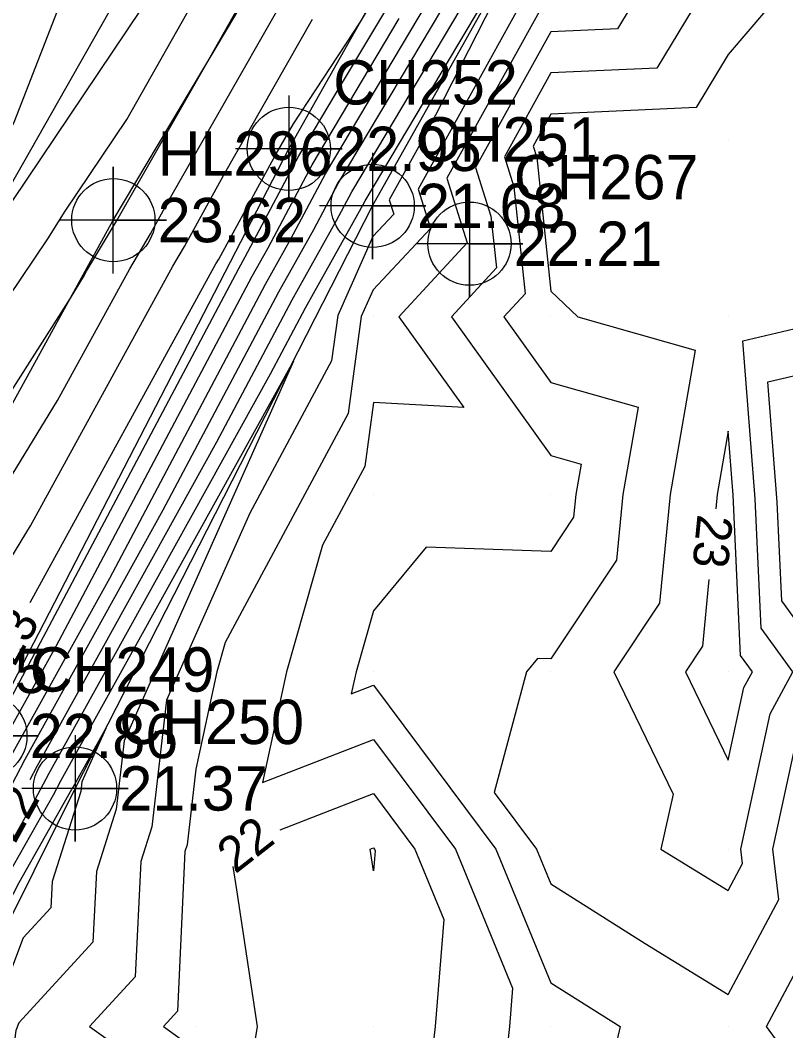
# Model space of a CAD drawing. Extents: x 2531902 to 2533249, y 715219 to 716099.
# Drawn here: x 2532990.1 to 2533033.2, y 715829.8 to 715886.7 of the extents above; entities that cross this region are included whole.
import ezdxf

# ---------------------------------------------------------------- set-up
doc = ezdxf.new("R2010")
doc.units = 0
for name, color, linetype in [('DTM Contours Major', 7, 'Continuous'), ('DTM Contours Major Text', 7, 'Continuous'), ('DTM Contours Minor', 7, 'Continuous'), ('Exist DTM Breakline', 7, 'Continuous'), ('Exist DTM Breakline Cogo Elevation', 7, 'Continuous'), ('Exist DTM Breakline Cogo Number', 7, 'Continuous'), ('Exist DTM Breakline Cogo Point CELL', 7, 'Continuous'), ('Exist DTM Crownline', 7, 'Continuous'), ('Exist DTM QL2 LIDAR Elevation Point', 7, 'Continuous'), ('Exist DTM Regular Point CELL', 7, 'Continuous'), ('Exist DTM Regular Point Cogo Elevation', 7, 'Continuous'), ('Exist DTM Regular Point Cogo Number', 7, 'Continuous'), ('Exist Roads Soil', 7, 'Continuous'), ('Exist Roads Soil Cogo Elevation', 7, 'Continuous'), ('Exist Roads Soil Cogo Number', 7, 'Continuous'), ('Exist Roads Soil Cogo Point CELL', 7, 'Continuous')]:
    doc.layers.add(name, color=color, linetype=linetype)

msp = doc.modelspace()

# ---------------------------------------------------------------- linework, layer by layer
at = {"layer": 'DTM Contours Major'}
for points in [[(2532990.662, 715853.905), (2533001.116, 715872.987), (2533001.281, 715873.262), (2533004.523, 715879.185), (2533005.496, 715880.892), (2533009.267, 715886.63), (2533020.429, 715905.293), (2533021.074, 715906.379), (2533026.439, 715915.352), (2533038.853, 715933.268), (2533043.166, 715938.88)], [(2532990.655, 715843.925), (2532991.049, 715844.672), (2533001.178, 715862.953), (2533005.423, 715870.964), (2533007.928, 715875.444), (2533008.784, 715877.059), (2533022.041, 715899.348), (2533024.099, 715902.789), (2533029.806, 715912.392), (2533030.202, 715913.056), (2533031.121, 715914.381), (2533034.622, 715918.936), (2533031.523, 715912.199), (2533031.803, 715911.11), (2533030.425, 715910.874), (2533029.087, 715908.137)], [(2533005.571, 715911.571), (2532998.047, 715902.991), (2532995.408, 715895.568), (2532989.728, 715880.959), (2532986.95, 715876.236), (2532986.539, 715875.537), (2532985.742, 715870.71), (2532989.489, 715876.266), (2532989.639, 715876.507), (2532996.946, 715887.377), (2533000.028, 715892.828), (2533012.634, 715915.667), (2533013.358, 715916.889)], [(2533027.331, 715904.543), (2533025.995, 715901.809), (2533021.382, 715893.7), (2533018.341, 715887.73), (2533012.518, 715877.211), (2533013.223, 715874.985), (2533009.99, 715871.533), (2533009.32, 715870.029), (2533008.579, 715864.548), (2533001.655, 715851.655), (2533001.185, 715850), (2533000, 715844.5), (2532999.506, 715840.248), (2532999.382, 715839.862), (2532998.953, 715830.858), (2532998.164, 715830), (2533000, 715828.691), (2533002.983, 715827.017), (2533003.468, 715830), (2533002.297, 715837.703), (2533002.097, 715839.013)], [(2533030.889, 715849.111), (2533031.362, 715850), (2533030.695, 715850.92), (2533030.286, 715859.954), (2533030, 715863.561), (2533029.386, 715860), (2533029.306, 715859.183)], [(2533028.916, 715855.202), (2533028.549, 715851.451), (2533027.584, 715850), (2533030, 715845.017), (2533030.889, 715849.111)], [(2533004.745, 715841.087), (2533010, 715843.128), (2533012.339, 715840), (2533013.966, 715836.034), (2533013.476, 715830), (2533013.132, 715826.868)]]:
    msp.add_lwpolyline(points, dxfattribs=at)
at = {"layer": 'DTM Contours Minor'}
for points in [[(2532973.429, 715821.806), (2532985.17, 715840.216), (2532985.68, 715841.188), (2532985.702, 715841.227), (2532988.35, 715846.252), (2532989.105, 715847.614), (2533002.414, 715872.733), (2533002.775, 715873.379), (2533005.803, 715879.089), (2533007.918, 715882.646), (2533021.163, 715904.792)], [(2532961.763, 715825.114), (2532974.339, 715842.999), (2532977.53, 715846.976), (2532977.892, 715847.481), (2532992.924, 715871.06), (2532993.711, 715872.349), (2532993.84, 715872.585), (2532995.525, 715875.39), (2532995.625, 715875.571), (2533000.473, 715884.078), (2533007.977, 715897.351)], [(2532980.806, 715896.056), (2532974.415, 715884.041), (2532975.418, 715873.531), (2532973.91, 715870.926), (2532973.877, 715870.057), (2532963.239, 715858.875), (2532955.103, 715841.953), (2532949.17, 715819.66), (2532959.725, 715827.976), (2532969.363, 715841.46), (2532973.494, 715847.335), (2532974.223, 715848.244), (2532975.261, 715849.693), (2532979.719, 715856.686), (2532991.661, 715874.393), (2532992.633, 715875.956), (2532996.105, 715881.12), (2533004.003, 715895.09)], [(2532923.186, 715712.886), (2532930.858, 715737.702), (2532931.519, 715738.867), (2532931.565, 715739.012), (2532935.901, 715749.684), (2532944.529, 715764.866), (2532949.298, 715771.05), (2532953.612, 715778.95), (2532962.696, 715793.355), (2532968.331, 715803.94), (2532968.918, 715804.969), (2532973.515, 715813.549), (2532977.321, 715820.404), (2532987.549, 715839.87), (2532988.835, 715842.147), (2532990.374, 715845.067), (2532998.16, 715859.118), (2533004.671, 715871.406), (2533006.64, 715874.927), (2533008.039, 715877.566), (2533018.511, 715895.173)], [(2532983.021, 715828.003), (2532988.794, 715838.992), (2532990.924, 715842.759), (2532991.724, 715844.277), (2533004.197, 715866.788), (2533006.175, 715870.522), (2533009.216, 715875.96), (2533009.53, 715876.551), (2533020.031, 715894.208), (2533013.028, 715880.457), (2533010.896, 715876.607), (2533011.155, 715875.792), (2533009.971, 715874.528), (2533007.992, 715870.086), (2533007.646, 715867.531), (2533003.034, 715858.943), (2532998.338, 715848.396), (2532997.507, 715841.252), (2532996.884, 715839.302), (2532996.574, 715832.805), (2532993.995, 715830), (2533000, 715825.719)], [(2532959.734, 715817.916), (2532974.936, 715838.353), (2532975.15, 715838.631), (2532975.249, 715838.787), (2532980.164, 715845.604), (2532980.606, 715846.309), (2532992.194, 715865.288), (2532996.266, 715872.719), (2532997.444, 715874.68), (2532998.591, 715876.776), (2533007.655, 715892.68)], [(2532916.168, 715709.807), (2532922.937, 715719.046), (2532928.431, 715736.817), (2532929.391, 715738.509), (2532929.424, 715738.615), (2532935.705, 715754.076), (2532941.15, 715763.655), (2532949.009, 715773.848), (2532952.572, 715780.372), (2532967.273, 715803.685), (2532967.59, 715804.529), (2532968.767, 715806.054), (2532972.987, 715813.931), (2532974.472, 715816.605), (2532986.926, 715840.31), (2532987.791, 715841.84), (2532989.699, 715845.462), (2532995.142, 715855.284), (2533003.918, 715871.848), (2533005.351, 715874.411), (2533007.293, 715878.074), (2533014.98, 715890.997)], [(2533026.016, 715890), (2533023.753, 715886.247), (2533020, 715886.078), (2533015.76, 715878.42), (2533016.628, 715875.68), (2533016.936, 715872.761), (2533014.398, 715870), (2533020, 715862.185), (2533021.703, 715861.703), (2533021.41, 715860), (2533021.284, 715858.716), (2533020, 715856.786), (2533012.981, 715857.019), (2533010, 715853.438), (2533009.024, 715850), (2533008.755, 715848.755), (2533010, 715849.239), (2533016.91, 715840), (2533020, 715832.466), (2533023.907, 715830), (2533022.077, 715822.077)], [(2533029.581, 715890), (2533025.977, 715884.023), (2533020, 715883.753), (2533017.382, 715879.024), (2533017.918, 715877.332), (2533018.552, 715871.304), (2533017.353, 715870), (2533020, 715866.307), (2533024.916, 715864.916), (2533024.068, 715860), (2533023.706, 715856.294), (2533020, 715850.723), (2533019.252, 715850.748), (2533018.629, 715850), (2533016.807, 715843.193), (2533019.195, 715840), (2533020, 715838.038), (2533025.319, 715834.681), (2533030, 715831.816), (2533032.845, 715837.155), (2533032.523, 715840), (2533033.857, 715846.143)], [(2533034.434, 715890), (2533030, 715884.784), (2533028.201, 715881.799), (2533020, 715881.429), (2533019.003, 715879.628), (2533019.207, 715878.984), (2533020, 715871.448), (2533021.517, 715870), (2533028.129, 715868.129), (2533026.727, 715860), (2533026.127, 715853.873), (2533023.551, 715850), (2533026.893, 715843.107), (2533026.201, 715840), (2533030, 715837.675), (2533030.808, 715839.192), (2533030.717, 715840), (2533032.373, 715847.627), (2533033.636, 715850), (2533031.855, 715852.456), (2533031.524, 715859.753), (2533030.819, 715868.651), (2533036.572, 715870)], [(2533020, 715888.402), (2533014.139, 715877.815), (2533015.292, 715874.177), (2533014.82, 715873.673), (2533011.443, 715870), (2533015.096, 715864.904), (2533010, 715865.179), (2533009.511, 715861.565), (2533007.129, 715857.129), (2533005.104, 715850), (2533003.76, 715843.76), (2533010, 715846.183), (2533014.625, 715840), (2533017.84, 715832.16), (2533017.665, 715830), (2533016.908, 715823.092)], [(2532910.432, 715708.479), (2532922.688, 715725.206), (2532926.003, 715735.932), (2532927.262, 715738.151), (2532927.284, 715738.218), (2532935.51, 715758.468), (2532937.77, 715762.445), (2532948.721, 715776.645), (2532951.532, 715781.795), (2532963.135, 715800.194), (2532965.619, 715806.809), (2532971.138, 715813.959), (2532972.856, 715816.197), (2532975.967, 715821.075), (2532986.303, 715840.749), (2532986.747, 715841.534), (2532989.025, 715845.857), (2532992.123, 715851.449), (2533003.166, 715872.291), (2533004.063, 715873.895), (2533006.548, 715878.581), (2533011.449, 715886.821)], [(2532913.805, 715732.275), (2532924.716, 715749.822), (2532927.378, 715756.907), (2532927.487, 715757.103), (2532937.989, 715777.463), (2532944.628, 715780.854), (2532947.854, 715785.038), (2532948.414, 715786.062), (2532950.722, 715789.722), (2532955.375, 715802.111), (2532959.105, 715812.252), (2532960.387, 715814.323), (2532965.555, 715821.271), (2532974.576, 715833.023), (2532978.776, 715839.609), (2532982.024, 715844.114), (2532983.417, 715846.335), (2532990.678, 715858.227), (2532998.691, 715872.853), (2532999.363, 715873.971), (2533001.557, 715877.98), (2533006.576, 715886.786)], [(2533035.909, 715850), (2533033.015, 715853.991), (2533032.763, 715859.553), (2533032.225, 715866.334), (2533039.416, 715868.02)], [(2532975.099, 715812.402), (2532985.871, 715831.803), (2532989.417, 715838.553), (2532991.968, 715843.066), (2532992.398, 715843.882), (2533005.491, 715867.511), (2532995.955, 715846.097), (2532995.509, 715842.255), (2532994.386, 715838.743), (2532994.196, 715834.752), (2532990.01, 715830.201), (2532989.853, 715829.785), (2532988.45, 715818.925)], [(2532975.627, 715812.02), (2532988.72, 715835.602), (2532990.04, 715838.113), (2532993.013, 715843.372), (2532993.073, 715843.487), (2532994.913, 715846.807), (2532993.573, 715843.798), (2532993.51, 715843.258), (2532991.888, 715838.184), (2532991.818, 715836.699), (2532990.261, 715835.006), (2532986.35, 715824.653)], [(2533010, 715838.778), (2533009.813, 715840), (2533010, 715840.072), (2533010.054, 715840), (2533010.092, 715839.908), (2533010, 715838.778)], [(2533038.009, 715821.991), (2533032.155, 715830), (2533034.882, 715835.118)]]:
    msp.add_lwpolyline(points, dxfattribs=at)
at = {"layer": 'Exist DTM Breakline'}
for points in [[(2532886.275, 715647.711), (2532887.831, 715646.823), (2532890.152, 715647.097), (2532894.459, 715651.173), (2532901.375, 715665.171), (2532911.098, 715687.189), (2532923.196, 715712.636), (2532936.336, 715739.896), (2532954.94, 715777.133), (2532972.649, 715814.175), (2532988.133, 715846.379), (2533005.236, 715879.474), (2533025.701, 715915.803), (2533049.322, 715952.267)], [(2532892.987, 715644.659), (2532898.123, 715649.312), (2532907.034, 715662.801), (2532916.799, 715684.707), (2532927.539, 715709.351), (2532941.275, 715737.303), (2532958.469, 715775.089), (2532977.032, 715811.003), (2532993.183, 715843.422), (2533009.96, 715876.258), (2533030.503, 715912.872), (2533054.575, 715948.316)]]:
    msp.add_lwpolyline(points, dxfattribs=at)
at = {"layer": 'Exist DTM Breakline Cogo Point CELL'}
for points in [[(2533005.236, 715882.474), (2533005.236, 715876.474), (2533005.236, 715879.474), (2533008.236, 715879.474), (2533002.236, 715879.474)], [(2533009.96, 715879.258), (2533009.96, 715873.258), (2533009.96, 715876.258), (2533012.96, 715876.258), (2533006.96, 715876.258)], [(2532988.133, 715849.379), (2532988.133, 715843.379), (2532988.133, 715846.379), (2532991.133, 715846.379), (2532985.133, 715846.379)], [(2532993.183, 715846.422), (2532993.183, 715840.422), (2532993.183, 715843.422), (2532996.183, 715843.422), (2532990.183, 715843.422)]]:
    msp.add_lwpolyline(points, dxfattribs=at)
for centre in [(2533005.236, 715879.474), (2533009.96, 715876.258), (2532988.133, 715846.379), (2532993.183, 715843.422)]:
    msp.add_circle(centre, 2.344, dxfattribs=at)
at = {"layer": 'Exist DTM Crownline'}
msp.add_lwpolyline([(2532876.571, 715652.013), (2532884.036, 715667.726), (2532897.268, 715696.346), (2532912.052, 715728.687), (2532925.335, 715755.88), (2532939.894, 715784.74), (2532958.948, 715822.246), (2532974.275, 715850.523), (2532997.485, 715891.381), (2533017.87, 715925.252), (2533038.842, 715957.692)], dxfattribs=at)
at = {"layer": 'Exist DTM QL2 LIDAR Elevation Point'}
for p, q in [((2533020, 715880), (2533020, 715880)), ((2533030, 715880), (2533030, 715880)), ((2533010, 715870), (2533010, 715870)), ((2533020, 715870), (2533020, 715870)), ((2533030, 715870), (2533030, 715870)), ((2533010, 715860), (2533010, 715860)), ((2533020, 715860), (2533020, 715860)), ((2533030, 715860), (2533030, 715860)), ((2533000, 715850), (2533000, 715850)), ((2533010, 715850), (2533010, 715850)), ((2533020, 715850), (2533020, 715850)), ((2533030, 715850), (2533030, 715850)), ((2533000, 715840), (2533000, 715840)), ((2533010, 715840), (2533010, 715840)), ((2533020, 715840), (2533020, 715840)), ((2533030, 715840), (2533030, 715840)), ((2533000, 715830), (2533000, 715830)), ((2533010, 715830), (2533010, 715830)), ((2533020, 715830), (2533020, 715830)), ((2533030, 715830), (2533030, 715830))]:
    msp.add_line(p, q, dxfattribs=at)
at = {"layer": 'Exist DTM Regular Point CELL'}
msp.add_lwpolyline([(2533015.417, 715877.129), (2533015.417, 715871.129), (2533015.417, 715874.129), (2533018.417, 715874.129), (2533012.417, 715874.129)], dxfattribs=at)
msp.add_circle((2533015.417, 715874.129), 2.344, dxfattribs=at)
at = {"layer": 'Exist Roads Soil'}
msp.add_lwpolyline([(2532882.435, 715649.375), (2532884.446, 715653.582), (2532893.832, 715673.236), (2532904.082, 715695.07), (2532909.886, 715707.279), (2532923.655, 715737.545), (2532935.371, 715761.586), (2532947.639, 715787.122), (2532960.723, 715812.473), (2532979.299, 715846.297), (2532995.343, 715875.457), (2533008.573, 715897.69), (2533027.701, 715928.616), (2533038.596, 715945.654), (2533044.798, 715955.275)], dxfattribs=at)
at = {"layer": 'Exist Roads Soil Cogo Point CELL'}
msp.add_lwpolyline([(2532995.343, 715872.457), (2532995.343, 715878.457), (2532995.343, 715875.457), (2532998.343, 715875.457), (2532992.343, 715875.457)], dxfattribs=at)
msp.add_circle((2532995.343, 715875.457), 2.344, dxfattribs=at)

# ---------------------------------------------------------------- texts
at = {"layer": 'DTM Contours Major Text'}
for s, rotation, p in [('23', 264.4096, (2533028.275, 715858.912)), ('23', 60.6923, (2532989.775, 715850.241)), ('22', 61.2255, (2532989.806, 715840.251)), ('22', 38.0691, (2533002.214, 715838.57))]:
    msp.add_text(s, height=2, rotation=rotation, dxfattribs=at).set_placement(p)
at = {"layer": 'Exist DTM Breakline Cogo Elevation'}
for s, p in [('22.95', (2533007.736, 715878.224)), ('21.68', (2533012.46, 715875.008)), ('22.86', (2532990.633, 715845.129)), ('21.37', (2532995.683, 715842.172))]:
    msp.add_text(s, height=2.5, dxfattribs=at).set_placement(p)
at = {"layer": 'Exist DTM Breakline Cogo Number'}
for s, p in [('CH252', (2533007.736, 715881.974)), ('CH251', (2533012.46, 715878.758)), ('CH249', (2532990.633, 715848.879)), ('CH250', (2532995.683, 715845.922))]:
    msp.add_text(s, height=2.5, dxfattribs=at).set_placement(p)
at = {"layer": 'Exist DTM Regular Point Cogo Elevation'}
msp.add_text('22.21', height=2.5, dxfattribs=at).set_placement((2533017.917, 715872.879))
at = {"layer": 'Exist DTM Regular Point Cogo Number'}
msp.add_text('CH267', height=2.5, dxfattribs=at).set_placement((2533017.917, 715876.629))
at = {"layer": 'Exist Roads Soil Cogo Elevation'}
msp.add_text('23.62', height=2.5, dxfattribs=at).set_placement((2532997.843, 715874.207))
at = {"layer": 'Exist Roads Soil Cogo Number'}
for s, p in [('HL296', (2532997.843, 715877.957)), ('HL295', (2532981.799, 715848.797))]:
    msp.add_text(s, height=2.5, dxfattribs=at).set_placement(p)

doc.saveas('drawing.dxf')
